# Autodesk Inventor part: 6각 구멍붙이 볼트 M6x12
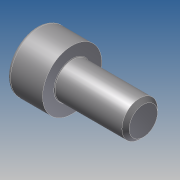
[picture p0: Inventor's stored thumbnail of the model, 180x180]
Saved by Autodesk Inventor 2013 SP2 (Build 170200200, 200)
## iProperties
Created: 2025-06
Part Number: 6각 구멍붙이 볼트 M6x12
Material: Generic
Document SubType Name: Modeling
Designer: i
Density: 1 g/cm^3
변환 표준: STEP AP214IS
전처리기: Build: 200, Release: 2013 SP2 Update 6 - Date: Thu 07/17/2014
전송 단위: 밀리미터
불확실성: 0.01
Author: i
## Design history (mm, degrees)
node "6각 구멍붙이 볼트 M6x121"
body "Solid1"
node "기준1"
